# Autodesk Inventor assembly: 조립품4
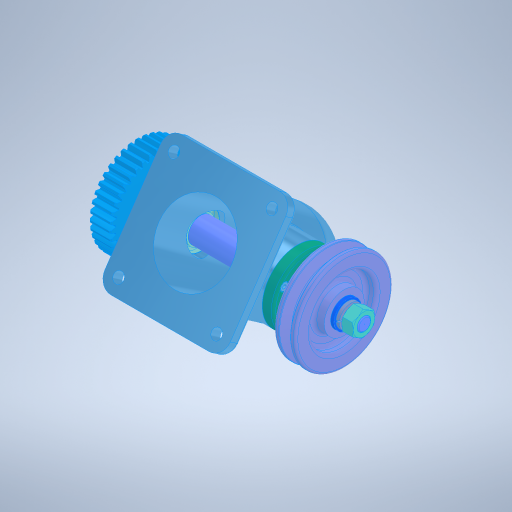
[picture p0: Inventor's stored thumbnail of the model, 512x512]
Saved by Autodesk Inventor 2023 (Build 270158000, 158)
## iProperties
Created: 2025-04
Part Number: 조립품4
Document SubType Name: Assembly
Designer: user
Author: user
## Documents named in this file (14)
- C:\Users\user\Desktop\750406V1015 유정현\조립품4.iam
- C:\Users\user\Desktop\750406V1015 유정현\본체.ipt
- C:\Users\user\Desktop\750406V1015 유정현\깊은 홈 볼 베어링 6203.ipt
- C:\Users\user\Desktop\750406V1015 유정현\축.ipt
- C:\Users\user\Desktop\750406V1015 유정현\커버.ipt
- C:\Users\user\Desktop\750406V1015 유정현\오일 실 26 38 8.ipt
- C:\Users\user\Desktop\750406V1015 유정현\6각 구멍붙이 볼트 M4x12.ipt
- C:\Users\user\Desktop\750406V1015 유정현\칼라.ipt
- C:\Users\user\Desktop\750406V1015 유정현\평행 키 5x5x12.ipt
- C:\Users\user\Desktop\750406V1015 유정현\스퍼기어.ipt
- C:\Users\user\Desktop\750406V1015 유정현\V 벨트 풀리.ipt
- C:\Users\user\Desktop\750406V1015 유정현\평와셔 M12.ipt
- C:\Users\user\Desktop\750406V1015 유정현\스프링 와셔 M12.ipt
- C:\Users\user\Desktop\750406V1015 유정현\6각 너트 M12x1.ipt
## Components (11 placed, 3 different names)
1. 6각 구멍붙이 볼트 M4x12:1
2. 6각 구멍붙이 볼트 M4x12:2
3. 6각 구멍붙이 볼트 M4x12:3
4. 6각 구멍붙이 볼트 M4x12:4
5. 6각 구멍붙이 볼트 M4x12:6
6. 6각 구멍붙이 볼트 M4x12:7
7. 6각 구멍붙이 볼트 M4x12:8
8. 6각 구멍붙이 볼트 M4x12:9
9. V 벨트 풀리:1
10. 6각 너트 M12x1:1
11. 6각 너트 M12x1:2
